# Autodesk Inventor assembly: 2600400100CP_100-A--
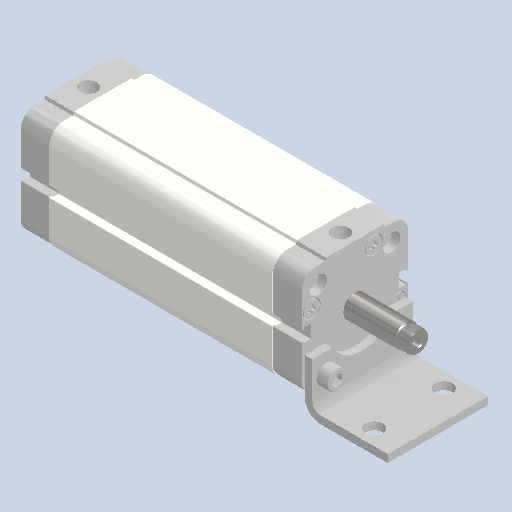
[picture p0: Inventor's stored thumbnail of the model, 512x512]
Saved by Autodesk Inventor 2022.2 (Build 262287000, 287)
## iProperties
Created: 2024-10
Part Number: 2600400100CP_100-A--
Document SubType Name: Assembly
Designer: 18907419
Author: 18907419
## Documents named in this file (7)
- C:\Users\18907419\Desktop\automazione\smistamento\2600400100CP_100-A--.iam
- C:\Users\18907419\Desktop\automazione\smistamento\260-40-CMPC-HF.ipt
- C:\Users\18907419\Desktop\automazione\smistamento\260-40_100-CMPC-BR.ipt
- C:\Users\18907419\Desktop\automazione\smistamento\260-40-CMPC-HR.ipt
- C:\Users\18907419\Desktop\automazione\smistamento\W0950402001-13_16.ipt
- C:\Users\18907419\Desktop\automazione\smistamento\Cylinder head screw DIN 912 M6x16.ipt
- C:\Users\18907419\Desktop\automazione\smistamento\260-40_100-CMPC-PR.ipt
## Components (7 placed, 6 different names)
1. 260-40-CMPC-HF:1
2. 260-40_100-CMPC-BR:1
3. 260-40-CMPC-HR:1
4. W0950402001-13_16:2
5. Cylinder head screw DIN 912 M6x16:3
6. Cylinder head screw DIN 912 M6x16:4
7. 260-40_100-CMPC-PR:1
